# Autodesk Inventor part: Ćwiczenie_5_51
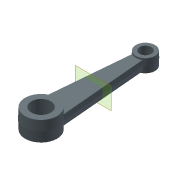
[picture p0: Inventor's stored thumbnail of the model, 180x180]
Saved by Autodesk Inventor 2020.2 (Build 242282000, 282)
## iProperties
Created: 2005-05
Part Number: Ćwiczenie_5_51
Document SubType Name: Modeling
Designer: F.Stasiak
Manufacturer: Standard
Standards Organization: Custom
Density: 1 g/cm^3
Material: Ogólny
Appearance: Niebieski szary (jasny)
Manager: www.cadconsulting.pl
Company: Fabian Stasiak CAD Consulting
Author: F.Stasiak
Subject: Zbiór ćwiczeń. Autodesk Inventor 2020. Kurs podstawowy
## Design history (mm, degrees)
sketch "Szkic3"
  geometry: C1 r 25 at (0, 0); 1 further point
  constraints: 1 centre point, 1 coincident
  dimensions: "d2" = 50 diameter of C1
extrude "Wyciągnięcie proste2" new body sketch "Szkic3" stored distance "d3" = 30; taper "d4" = -2 deg
sketch "Szkic4"
  geometry: L1 (0, 0)-(0, 160); C1 r 24.476 at (0, 0) reference; C2 r 15 at (0, 160)
  constraints: 2 end point, 1 centre point, 1 coincident, 1 vertical
  dimensions: "d5" = 30 diameter of C2; "d13" = 160 distance of L1.start C2.centre
extrude "Wyciągnięcie proste3" join sketch "Szkic4" stored distance "d6" = 20; taper "d7" = -2 deg
sketch "Szkic5"
  geometry: L1 (-7.5, 160)-(-21.498, 0); L2 (7.5, 160)-(21.498, 0); L3 (-7.5, 160)-(7.5, 160); L4 (-21.498, 0)-(21.498, 0); C1 r 24.476 at (0, 0) reference; C2 r 14.651 at (0, 160) reference; 2 further points
  constraints: 8 end point, 2 coincident, 2 horizontal, 2 midpoint
  dimensions: "d8" = 10 deg angle of L2 L1; "d15" = 15 distance of L1.start L2.start
extrude "Wyciągnięcie proste4" join sketch "Szkic5" stored distance "d10" = 15; taper "d11" = -5 deg
node "Płaszczyzna konstrukcyjna1"
sketch "Szkic6"
  geometry: C1 r 24.476 at (0, 0) reference
hole "Otwór1" sketch "Szkic6" at (0, 0) diameter "d25" = 30; stored, may be unused: countersink angle "d29" = 90 deg, drill point angle "d31" = 118 deg; dims "d26" = 6, "d27" = 4, "d28" = 2, "d30" = 8
sketch "Szkic7"
  geometry: C1 r 14.651 at (0, 0) reference
hole "Otwór2" sketch "Szkic7" at (0, 0) diameter "d32" = 18; stored, may be unused: countersink angle "d36" = 90 deg, drill point angle "d38" = 118 deg; dims "d33" = 6, "d34" = 4, "d35" = 2, "d37" = 8
node "Bryła1"
node "Korpusy bryłowe"
node "Korpusy powierzchniowe"
node "Pętla rzutowana2"
node "Pętla rzutowana3"
